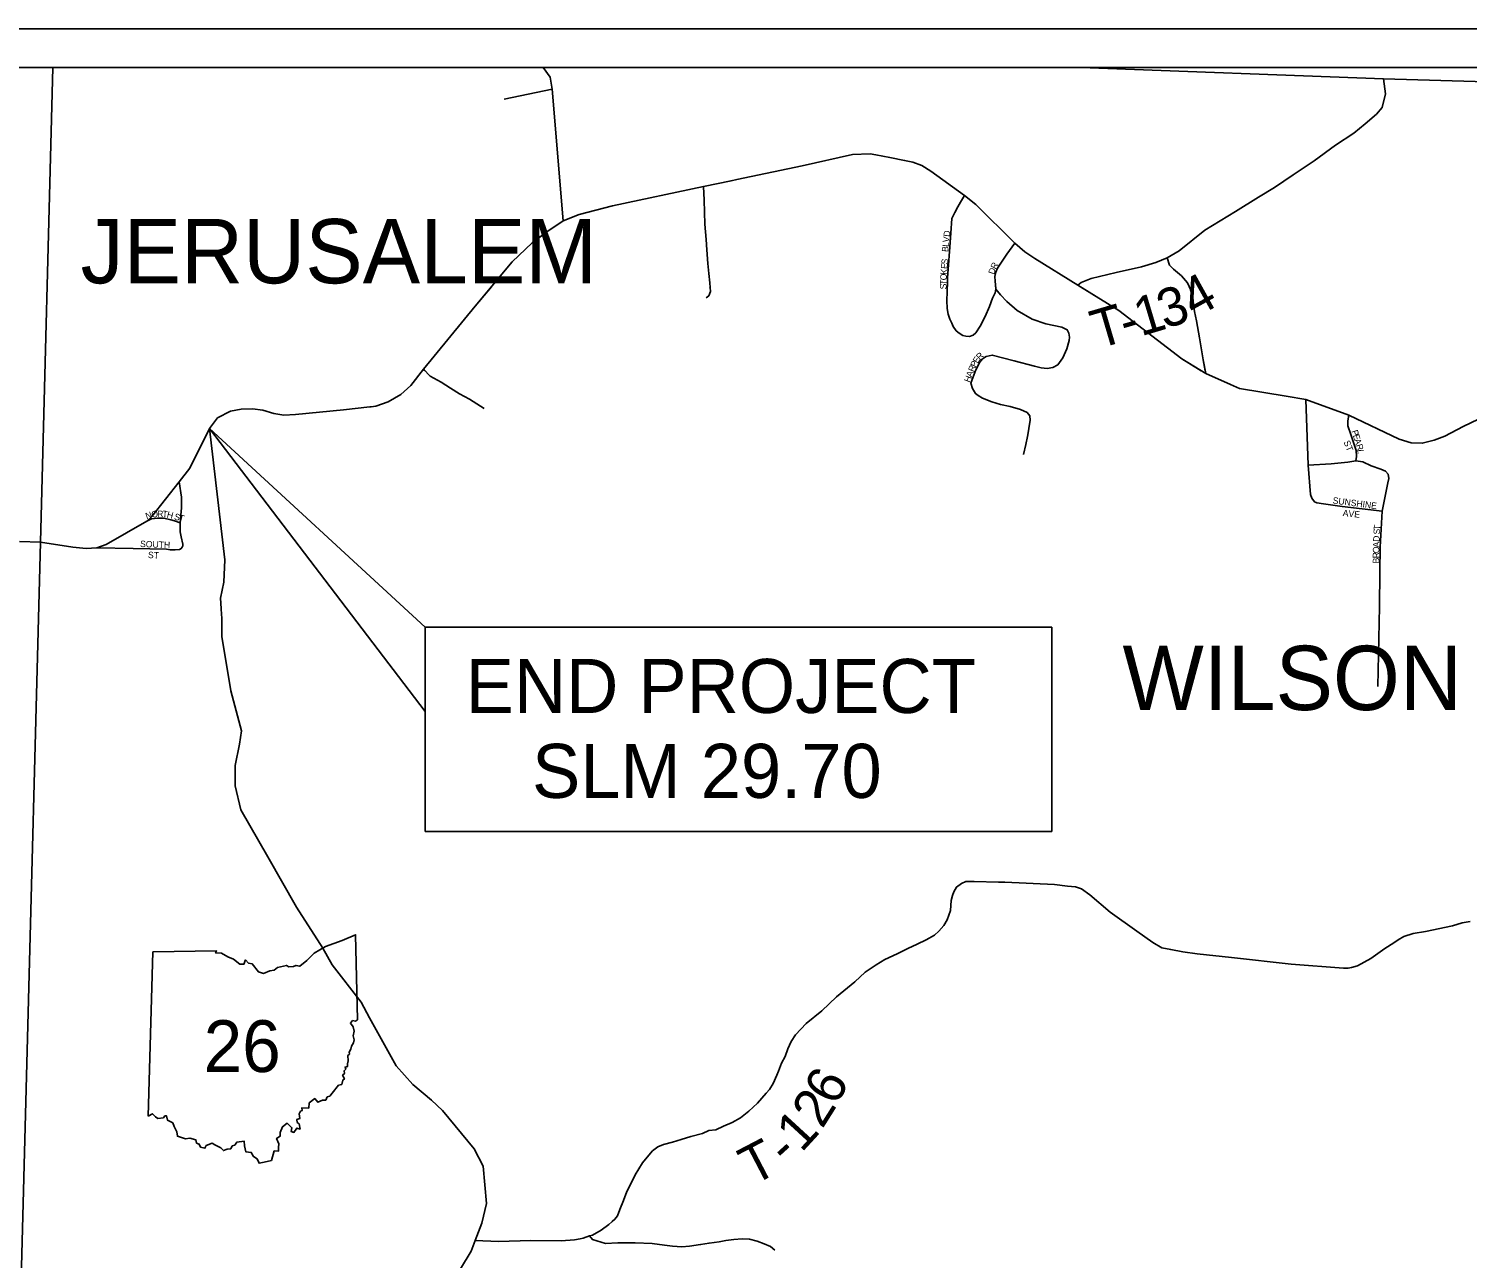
# Model space of a CAD drawing. Extents: x -15 to 405, y -40 to 87.
# Drawn here: x -11.331 to -9.096, y 40.271 to 42.183 of the extents above; entities that cross this region are included whole.
import ezdxf

# ---------------------------------------------------------------- set-up
doc = ezdxf.new("R2010")
doc.units = 0
for name, color, linetype in [('GM_P_State_Location', 7, 'Continuous'), ('GM_X_Airport_Text_Class_2', 7, 'Continuous'), ('GM_X_City_Street_Text', 7, 'Continuous'), ('GM_X_Major_Lake', 7, 'Continuous'), ('GM_X_Major_Lake_Text', 7, 'Continuous'), ('GM_X_Major_River', 7, 'Continuous'), ('GM_X_Minor_River', 7, 'Continuous'), ('GM_X_Rail_Line', 7, 'Continuous'), ('GM_X_State_Location', 7, 'Continuous'), ('GM_X_State_Route', 7, 'Continuous'), ('GM_X_State_Shield', 7, 'Continuous'), ('GM_X_Township_ROW', 7, 'Continuous')]:
    doc.layers.add(name, color=color, linetype=linetype)

msp = doc.modelspace()

# ---------------------------------------------------------------- linework, layer by layer
at = {"layer": 'GM_P_State_Location'}
for points in [[(-9.7009, 41.7839), (-9.6961, 41.7879), (-9.6802, 41.7941), (-9.6414, 41.8038), (-9.6022, 41.8127), (-9.5798, 41.8194), (-9.5624, 41.8265), (-9.5436, 41.8375), (-9.5039, 41.8697), (-9.4561, 41.8984), (-9.4203, 41.9205), (-9.3956, 41.9357), (-9.3666, 41.9553), (-9.334, 41.9774), (-9.3006, 42.0014), (-9.2723, 42.0202), (-9.2545, 42.0349), (-9.237, 42.05), (-9.2283, 42.0601), (-9.223, 42.0814), (-9.226, 42.1046)], [(-10.2826, 41.9373), (-10.2815, 41.9163), (-10.2807, 41.879), (-10.2788, 41.855), (-10.2774, 41.8389), (-10.2759, 41.8177), (-10.2745, 41.8021), (-10.2731, 41.7877), (-10.2726, 41.7805), (-10.2721, 41.7741), (-10.2745, 41.7676), (-10.2784, 41.7644)], [(-9.5032, 41.6509), (-9.5062, 41.6677), (-9.5122, 41.7021), (-9.5169, 41.7285), (-9.5199, 41.7428), (-9.5213, 41.7536), (-9.5218, 41.7609), (-9.5239, 41.7696), (-9.5268, 41.7788), (-9.5309, 41.7876), (-9.5403, 41.7987), (-9.5524, 41.809), (-9.5585, 41.8149), (-9.5624, 41.8265)], [(-10.2727, 41.7814), (-10.2726, 41.7805), (-10.2721, 41.7741), (-10.2745, 41.7676), (-10.2784, 41.7644)], [(-9.5025, 41.6467), (-9.5062, 41.6677), (-9.5122, 41.7021), (-9.5169, 41.7285), (-9.5199, 41.7428), (-9.5213, 41.7536), (-9.5218, 41.7609), (-9.5239, 41.7696), (-9.5268, 41.7788), (-9.528, 41.7814)], [(-10.718, 41.6532), (-10.7072, 41.6424), (-10.6902, 41.6333), (-10.6757, 41.6239), (-10.6619, 41.6153), (-10.6462, 41.607), (-10.6235, 41.5921)], [(-10.718, 41.6532), (-10.7158, 41.6509)], [(-10.4253, 40.3279), (-10.4244, 40.3287), (-10.4204, 40.332), (-10.4165, 40.3373), (-10.4126, 40.3474), (-10.4071, 40.361), (-10.4016, 40.3751), (-10.3958, 40.3872), (-10.3891, 40.4013), (-10.3832, 40.4102), (-10.3777, 40.4199), (-10.3678, 40.4316), (-10.3618, 40.4385), (-10.3539, 40.4446), (-10.3447, 40.4483), (-10.3311, 40.4521), (-10.3175, 40.4558), (-10.3023, 40.4608), (-10.2843, 40.4654), (-10.2743, 40.4699), (-10.2635, 40.4712), (-10.2519, 40.4766), (-10.238, 40.4827), (-10.2252, 40.4897), (-10.2121, 40.5002), (-10.199, 40.5124), (-10.1855, 40.5282), (-10.1804, 40.5339), (-10.1745, 40.5431), (-10.1686, 40.556), (-10.1662, 40.5625), (-10.1616, 40.5749), (-10.1561, 40.585), (-10.1518, 40.5971), (-10.1467, 40.6084), (-10.14, 40.6185), (-10.1233, 40.6363), (-10.0987, 40.6558), (-10.076, 40.6777), (-10.0474, 40.7013), (-10.0315, 40.7159), (-10.0144, 40.7277), (-10.0009, 40.7358), (-9.9817, 40.7445), (-9.9654, 40.7527), (-9.951, 40.7596), (-9.937, 40.7666), (-9.9239, 40.7736), (-9.9171, 40.78), (-9.9092, 40.7889), (-9.9041, 40.7974), (-9.899, 40.8119), (-9.898, 40.8276), (-9.8961, 40.8352), (-9.8937, 40.8408), (-9.8898, 40.8485), (-9.8818, 40.8538), (-9.8754, 40.8571), (-9.8622, 40.8568), (-9.8244, 40.8562)], [(-9.8244, 40.8562), (-9.8169, 40.8561), (-9.8148, 40.856), (-9.7374, 40.8526), (-9.717, 40.8496), (-9.7049, 40.8489), (-9.6957, 40.8458), (-9.6827, 40.8363), (-9.6508, 40.8094), (-9.6096, 40.7798), (-9.5845, 40.762), (-9.5708, 40.7542), (-9.5567, 40.7511), (-9.5378, 40.7477), (-9.5158, 40.7447), (-9.4624, 40.7389), (-9.3696, 40.7287), (-9.2882, 40.7224), (-9.2809, 40.7225), (-9.2757, 40.7233), (-9.2666, 40.7262), (-9.2458, 40.7373), (-9.2243, 40.7528), (-9.2104, 40.7617), (-9.2036, 40.7666), (-9.1945, 40.7715), (-9.1801, 40.7761), (-9.1609, 40.7795), (-9.1192, 40.7884), (-9.104, 40.7926), (-9.0916, 40.7947)], [(-10.6375, 40.2989), (-10.6013, 40.2976), (-10.5512, 40.299), (-10.5039, 40.2987), (-10.483, 40.3001), (-10.4742, 40.3018), (-10.4698, 40.3026), (-10.4599, 40.3064), (-10.4551, 40.3072), (-10.4415, 40.315), (-10.43, 40.3239), (-10.4253, 40.3279)], [(-10.4599, 40.3064), (-10.4554, 40.3008), (-10.4349, 40.2942), (-10.416, 40.2956), (-10.3888, 40.2955), (-10.3627, 40.2942), (-10.3434, 40.2916), (-10.331, 40.2901), (-10.3165, 40.2894), (-10.3045, 40.29), (-10.2873, 40.2926), (-10.2741, 40.2951), (-10.2585, 40.2969), (-10.2481, 40.299), (-10.2357, 40.3007), (-10.2228, 40.3017), (-10.2112, 40.301), (-10.1995, 40.2979), (-10.1883, 40.294), (-10.1786, 40.2897), (-10.1717, 40.2838)]]:
    msp.add_lwpolyline(points, dxfattribs=at)
at = {"layer": 'GM_X_City_Street_Text'}
for points in [[(-9.877, 41.9232), (-9.8833, 41.9131), (-9.8876, 41.9055), (-9.8924, 41.8971), (-9.8968, 41.8878), (-9.8986, 41.8646), (-9.9005, 41.8365), (-9.902, 41.8156), (-9.9035, 41.7952), (-9.9036, 41.7893)], [(-9.8602, 41.6509), (-9.8597, 41.6523), (-9.8534, 41.6644), (-9.8494, 41.6692), (-9.8434, 41.6733), (-9.8342, 41.6753), (-9.8, 41.6663), (-9.7687, 41.6581), (-9.7579, 41.6554), (-9.7487, 41.6546), (-9.7402, 41.6559), (-9.7322, 41.6603), (-9.7243, 41.6708), (-9.7183, 41.6849), (-9.7144, 41.6981), (-9.7142, 41.7031), (-9.7149, 41.7094), (-9.7177, 41.7146), (-9.7262, 41.7185), (-9.7507, 41.724), (-9.7719, 41.7311), (-9.7953, 41.7445), (-9.8114, 41.7585), (-9.8211, 41.7688), (-9.8284, 41.7776), (-9.8292, 41.7844), (-9.8296, 41.7904), (-9.8301, 41.7976), (-9.8285, 41.8041), (-9.8257, 41.8105), (-9.8114, 41.8322), (-9.7991, 41.8495)], [(-9.9036, 41.7893), (-9.9036, 41.7893), (-9.9041, 41.7735), (-9.9045, 41.7603), (-9.904, 41.7475), (-9.9027, 41.7391), (-9.8999, 41.7311), (-9.897, 41.7251), (-9.8946, 41.7199), (-9.8901, 41.7131), (-9.8857, 41.7091), (-9.8797, 41.7059), (-9.8749, 41.7048), (-9.8692, 41.7044), (-9.8636, 41.706), (-9.8597, 41.7101), (-9.8529, 41.7201), (-9.845, 41.7354), (-9.8382, 41.7507), (-9.8335, 41.7635), (-9.8295, 41.772), (-9.8284, 41.7776)], [(-9.9039, 41.7814), (-9.9041, 41.7735), (-9.9045, 41.7603), (-9.904, 41.7475), (-9.9027, 41.7391), (-9.8999, 41.7311), (-9.897, 41.7251), (-9.8946, 41.7199), (-9.8901, 41.7131), (-9.8857, 41.7091), (-9.8797, 41.7059), (-9.8749, 41.7048), (-9.8692, 41.7044), (-9.8636, 41.706), (-9.8597, 41.7101), (-9.8529, 41.7201), (-9.845, 41.7354), (-9.8382, 41.7507), (-9.8335, 41.7635), (-9.8295, 41.772), (-9.8284, 41.7776)], [(-9.7856, 41.5205), (-9.7821, 41.5362), (-9.7793, 41.5486), (-9.7778, 41.5574), (-9.7766, 41.5647), (-9.7758, 41.5703), (-9.7751, 41.5743), (-9.7759, 41.5807), (-9.7799, 41.5863), (-9.79, 41.5906), (-9.8065, 41.5954), (-9.8213, 41.5985), (-9.8346, 41.6028), (-9.849, 41.6083), (-9.8559, 41.6123), (-9.8603, 41.6155), (-9.8648, 41.6231), (-9.8672, 41.6315), (-9.8597, 41.6523), (-9.8534, 41.6644), (-9.8494, 41.6692), (-9.8434, 41.6733), (-9.8342, 41.6753), (-9.8, 41.6663), (-9.7687, 41.6581), (-9.7579, 41.6554), (-9.7487, 41.6546), (-9.7402, 41.6559), (-9.7322, 41.6603), (-9.7243, 41.6708), (-9.7183, 41.6849), (-9.7144, 41.6981), (-9.7142, 41.7031), (-9.7149, 41.7094), (-9.7177, 41.7146), (-9.7262, 41.7185), (-9.7507, 41.724), (-9.7719, 41.7311), (-9.7953, 41.7445), (-9.8114, 41.7585), (-9.8211, 41.7688), (-9.8284, 41.7776), (-9.8288, 41.7814)], [(-11.2251, 41.3759), (-11.1686, 41.3749), (-11.1168, 41.3736), (-11.1112, 41.3728), (-11.1037, 41.3728), (-11.0968, 41.3733), (-11.0941, 41.3746), (-11.0925, 41.3765), (-11.0916, 41.3786), (-11.0916, 41.3814), (-11.0941, 41.393), (-11.0958, 41.4006), (-11.0958, 41.4058), (-11.0956, 41.4146), (-11.094, 41.4379), (-11.0937, 41.4543), (-11.0976, 41.4784)], [(-11.1475, 41.4171), (-11.1404, 41.4208), (-11.1312, 41.4216), (-11.1215, 41.4217), (-11.1147, 41.4205), (-11.1103, 41.4193), (-11.1047, 41.4174), (-11.0956, 41.4146)]]:
    msp.add_lwpolyline(points, dxfattribs=at)
at = {"layer": 'GM_X_Major_Lake_Text'}
msp.add_lwpolyline([(-10.5924, 42.0733), (-10.5178, 42.0887)], dxfattribs=at)
at = {"layer": 'GM_X_Major_River'}
for points in [[(-9.2283, 41.4327), (-9.2902, 41.4399), (-9.3195, 41.4443), (-9.3299, 41.4457), (-9.3332, 41.4473), (-9.3376, 41.4528), (-9.3397, 41.4584), (-9.3431, 41.504), (-9.3471, 41.6061)], [(-9.2691, 41.5111), (-9.268, 41.5175), (-9.2685, 41.5271), (-9.2768, 41.5519), (-9.2818, 41.5654), (-9.2815, 41.5731), (-9.2799, 41.5818)], [(-9.3431, 41.504), (-9.3075, 41.5061), (-9.2819, 41.5089), (-9.2691, 41.5111), (-9.2582, 41.5096), (-9.2453, 41.503), (-9.2304, 41.498), (-9.2231, 41.4949), (-9.2191, 41.4902), (-9.218, 41.4836), (-9.2193, 41.4768), (-9.2283, 41.4327), (-9.2316, 41.3765), (-9.2319, 41.3388)], [(-9.2319, 41.3388), (-9.2319, 41.3379), (-9.2323, 41.2843), (-9.235, 41.1604)]]:
    msp.add_lwpolyline(points, dxfattribs=at)
at = {"layer": 'GM_X_Rail_Line'}
msp.add_lwpolyline([(-5.8735, 37.6193), (-6.746, 37.6435), (-7.1795, 37.6523), (-7.1958, 37.2443), (-7.727, 37.2683), (-7.6952, 37.7971), (-8.9152, 37.8499), (-9.0187, 37.8511), (-9.126, 37.86), (-10.3436, 37.8843), (-11.1424, 37.9093), (-11.1367, 38.1803), (-11.3964, 38.1863), (-11.3573, 39.6853), (-11.313, 41.3844), (-11.2938, 42.1225)], dxfattribs=at)
at = {"layer": 'GM_X_State_Location'}
for p, q in [((-14.8813, 42.1225), (-5.8856, 42.1225)), ((-10.7153, 40.9349), (-10.7153, 41.2523)), ((-10.7153, 41.2523), (-9.7415, 41.2523)), ((-9.7415, 41.2523), (-9.7415, 40.9349)), ((-9.7415, 40.9349), (-10.7153, 40.9349)), ((-11.1455, 40.4922), (-11.1383, 40.7475))]:
    msp.add_line(p, q, dxfattribs=at)
for points in [[(-14.9291, 34.0044), (-14.9414, 42.1825), (-5.8257, 42.1825), (-5.8134, 34.0044)], [(-10.7153, 41.2523), (-11.0504, 41.5612), (-10.7153, 41.1212)]]:
    msp.add_lwpolyline(points, close=True, dxfattribs=at)
for points in [[(-10.5007, 41.884), (-10.5178, 42.0887), (-10.521, 42.1073), (-10.5319, 42.1225)], [(-10.231, 41.9482), (-10.1294, 41.9695), (-10.0511, 41.9873), (-10.0239, 41.9882), (-10.0148, 41.9865), (-9.9933, 41.9823)], [(-9.9933, 41.9823), (-9.9704, 41.9779), (-9.9575, 41.9752), (-9.9436, 41.97), (-9.9297, 41.9614), (-9.877, 41.9232), (-9.8594, 41.9093), (-9.7991, 41.8495), (-9.7837, 41.836), (-9.7678, 41.8256), (-9.7009, 41.7839)], [(-10.5007, 41.884), (-10.476, 41.8936), (-10.4241, 41.9074), (-10.2826, 41.9373), (-10.24, 41.9463), (-10.231, 41.9482)], [(-10.7198, 41.6509), (-10.718, 41.6532), (-10.6377, 41.7511), (-10.58, 41.82), (-10.5487, 41.8496), (-10.5263, 41.867), (-10.5007, 41.884)], [(-10.8009, 41.5948), (-10.7992, 41.5949), (-10.7918, 41.5957), (-10.7724, 41.6025), (-10.7531, 41.6139), (-10.7377, 41.6281), (-10.718, 41.6532), (-10.6377, 41.7511), (-10.6123, 41.7814)], [(-9.7009, 41.7839), (-9.6373, 41.7445), (-9.5394, 41.6697), (-9.5093, 41.6509)], [(-9.6969, 41.7814), (-9.6373, 41.7445), (-9.5394, 41.6697), (-9.5025, 41.6467), (-9.4642, 41.6298)], [(-9.4642, 41.6298), (-9.45, 41.6236), (-9.3776, 41.6116), (-9.3471, 41.6061), (-9.2799, 41.5818), (-9.2017, 41.5446), (-9.1835, 41.539), (-9.166, 41.5383), (-9.1474, 41.5428), (-9.1312, 41.5491), (-9.1026, 41.5644), (-9.0788, 41.5755)], [(-11.0504, 41.5612), (-11.0378, 41.5779), (-11.0178, 41.5881), (-11.0013, 41.5912), (-10.9834, 41.5918), (-10.9672, 41.5897), (-10.9504, 41.5846), (-10.9348, 41.5819), (-10.9166, 41.5828), (-10.8423, 41.5903), (-10.8009, 41.5948)], [(-11.3456, 41.3857), (-11.313, 41.3844), (-11.2628, 41.3768), (-11.2421, 41.3746), (-11.2251, 41.3759), (-11.2109, 41.3807), (-11.1475, 41.4171), (-11.1399, 41.4242), (-11.0976, 41.4784), (-11.0806, 41.4994), (-11.0504, 41.5612)], [(-11.0319, 41.2805), (-11.032, 41.2814), (-11.0331, 41.2977), (-11.0279, 41.3223), (-11.0265, 41.3572), (-11.0504, 41.5612)], [(-10.6602, 40.2548), (-10.6438, 40.2823), (-10.6375, 40.2989), (-10.6273, 40.3259), (-10.6198, 40.3565), (-10.6252, 40.4146), (-10.6393, 40.4416), (-10.6884, 40.5009), (-10.7055, 40.5171), (-10.7344, 40.5414), (-10.7602, 40.5706), (-10.8015, 40.6453), (-10.8147, 40.6695), (-10.8598, 40.7273), (-10.8743, 40.7535), (-10.9151, 40.817), (-10.9597, 40.8952), (-11.0014, 40.9682), (-11.0105, 41.0058), (-11.0106, 41.0371), (-11.0036, 41.0705), (-11.0007, 41.0914), (-11.017, 41.1536), (-11.0313, 41.238), (-11.0309, 41.2661), (-11.0319, 41.2805)], [(-11.1383, 40.7475), (-11.0393, 40.7491), (-11.0408, 40.746), (-11.0315, 40.7454), (-11.0216, 40.7399), (-11.0132, 40.7365), (-11.0029, 40.7284), (-10.9968, 40.7284), (-10.9942, 40.7351), (-10.9895, 40.73), (-10.9839, 40.729), (-10.9742, 40.7168), (-10.9663, 40.7142), (-10.9567, 40.7184), (-10.9496, 40.7191), (-10.9444, 40.7232), (-10.9308, 40.7267), (-10.927, 40.7246), (-10.9198, 40.7251), (-10.9161, 40.7266), (-10.9099, 40.7252), (-10.8989, 40.7345), (-10.8875, 40.7455), (-10.87, 40.7558), (-10.8439, 40.7655), (-10.8232, 40.7743), (-10.8202, 40.6418)], [(-10.8202, 40.6418), (-10.8233, 40.64), (-10.828, 40.6408), (-10.8312, 40.6371), (-10.8272, 40.6309), (-10.8254, 40.6244), (-10.827, 40.6172), (-10.8254, 40.6112), (-10.8265, 40.6062), (-10.8295, 40.6013), (-10.8305, 40.5966), (-10.8331, 40.5916), (-10.8329, 40.5888), (-10.8352, 40.5866), (-10.8348, 40.5783), (-10.836, 40.5737), (-10.8356, 40.5697), (-10.8396, 40.5687), (-10.8386, 40.5654), (-10.8411, 40.5629), (-10.8406, 40.5586), (-10.8435, 40.5558), (-10.8407, 40.5502), (-10.8429, 40.5485), (-10.8447, 40.5417), (-10.8498, 40.5403), (-10.8598, 40.528), (-10.8634, 40.5233), (-10.8674, 40.5221), (-10.8696, 40.5173), (-10.8745, 40.5173), (-10.882, 40.514), (-10.8868, 40.5197), (-10.8952, 40.5128), (-10.8961, 40.5048), (-10.9068, 40.5051), (-10.9064, 40.5011), (-10.9088, 40.4999), (-10.9109, 40.4959), (-10.9097, 40.4887), (-10.9147, 40.4869), (-10.9141, 40.4827), (-10.9108, 40.4802), (-10.9094, 40.4722), (-10.9147, 40.4738), (-10.9191, 40.4671), (-10.9236, 40.4687), (-10.9221, 40.4744), (-10.9296, 40.4812), (-10.9368, 40.4758), (-10.9405, 40.467), (-10.9405, 40.4611), (-10.9459, 40.4576), (-10.9424, 40.4493), (-10.9431, 40.4436), (-10.943, 40.4381), (-10.9496, 40.4384), (-10.9537, 40.4236)], [(-10.9537, 40.4236), (-10.9652, 40.4208), (-10.9732, 40.4192), (-10.9761, 40.4258), (-10.9818, 40.4294), (-10.9855, 40.436), (-10.9938, 40.437), (-10.9957, 40.4462), (-10.9966, 40.4536), (-11.0079, 40.4518), (-11.011, 40.4472), (-11.015, 40.446), (-11.0173, 40.4414), (-11.0228, 40.441), (-11.0286, 40.4388), (-11.0324, 40.4433), (-11.042, 40.4479), (-11.0463, 40.4502), (-11.0553, 40.4466), (-11.0573, 40.4423), (-11.0644, 40.4442), (-11.0661, 40.449), (-11.0704, 40.4505), (-11.0714, 40.4555), (-11.0806, 40.4583), (-11.0877, 40.4572), (-11.1002, 40.4612), (-11.101, 40.4679), (-11.1052, 40.4761), (-11.1074, 40.4817), (-11.1153, 40.486), (-11.117, 40.4928), (-11.1195, 40.4926), (-11.1218, 40.4899), (-11.1306, 40.4886), (-11.1341, 40.4913), (-11.139, 40.4961), (-11.1455, 40.4922)]]:
    msp.add_lwpolyline(points, dxfattribs=at)
at = {"layer": 'GM_X_State_Route'}
msp.add_lwpolyline([(-5.8852, 41.8593), (-6.0144, 41.8658), (-7.0055, 41.8974), (-6.9927, 42.0179), (-7.1063, 42.0243), (-7.8445, 42.0517), (-8.0815, 42.0605), (-8.6025, 42.0864), (-9.226, 42.1046), (-9.6959, 42.1225)], dxfattribs=at)

# ---------------------------------------------------------------- texts
at = {"layer": 'GM_X_Airport_Text_Class_2'}
for s, rotation, p in [('V', 83.8457, (-9.9011, 41.8501)), ('D', 83.8239, (-9.9001, 41.8588)), ('B', 84.6495, (-9.9026, 41.8352)), ('L', 83.868, (-9.9018, 41.8431)), ('E', 84.8006, (-9.904, 41.8088)), ('S', 84.7734, (-9.9033, 41.8158)), ('R', 62.6204, (-9.8285, 41.8078)), ('O', 87.3111, (-9.9051, 41.7913)), ('K', 85.1637, (-9.9047, 41.8)), ('D', 71.0535, (-9.8312, 41.7998)), ('S', 89.5902, (-9.9052, 41.7774)), ('T', 89.5628, (-9.9052, 41.7844)), ('R', 67.4231, (-9.8628, 41.6483)), ('P', 63.6427, (-9.8598, 41.6554)), ('P', 63.6427, (-9.8598, 41.6554)), ('E', 57.2648, (-9.8568, 41.6615)), ('E', 57.2648, (-9.8568, 41.6615)), ('R', 43.6949, (-9.8534, 41.6669)), ('R', 43.6949, (-9.8534, 41.6669)), ('H', 69.1241, (-9.869, 41.6319)), ('A', 69.1037, (-9.8659, 41.6401)), ('N', 18.5041, (-11.1478, 41.4199)), ('O', 6.3957, (-11.14, 41.4226)), ('R', 0.4129, (-11.1315, 41.4235)), ('T', 355.5426, (-11.1238, 41.4236)), ('H', 345.0573, (-11.1173, 41.4231)), ('S', 344.2841, (-11.1059, 41.4199)), ('T', 346.2869, (-11.0988, 41.4179)), ('SOUTH', 357.5069, (-11.1583, 41.377)), ('ST', 356.4118, (-11.1461, 41.3599))]:
    msp.add_text(s, height=0.01, rotation=rotation, dxfattribs=at).set_placement(p)
at = {"layer": 'GM_X_Major_Lake'}
for s, rotation, p in [('P', 287.5969, (-9.2761, 41.5571)), ('E', 287.5708, (-9.274, 41.5504)), ('ST', 291.7989, (-9.2885, 41.5403)), ('A', 287.5796, (-9.2719, 41.5437)), ('R', 287.5816, (-9.2692, 41.5353)), ('L', 273.9649, (-9.2669, 41.5284)), ('SUNSHINE', 352.5664, (-9.3057, 41.4447)), ('AVE', 354.0969, (-9.2899, 41.4251)), ('D', 87.1354, (-9.2325, 41.3848)), ('S', 87.0872, (-9.2319, 41.3962)), ('T', 87.0475, (-9.2315, 41.4032)), ('O', 89.8251, (-9.2328, 41.3673)), ('R', 89.8279, (-9.2329, 41.3594)), ('A', 87.8142, (-9.2328, 41.376)), ('B', 89.83, (-9.2329, 41.3515))]:
    msp.add_text(s, height=0.01, rotation=rotation, dxfattribs=at).set_placement(p)
at = {"layer": 'GM_X_Minor_River'}
for s, rotation, p in [('4', 29.0753, (-9.5197, 41.7319)), ('3', 18.3212, (-9.566, 41.7154)), ('T', 16.4193, (-9.6701, 41.6845)), ('T', 16.4193, (-9.6701, 41.6845)), ('1', 16.6626, (-9.6032, 41.7042)), ('1', 16.6626, (-9.6032, 41.7042)), ('-', 16.4543, (-9.6271, 41.6972)), ('-', 16.4543, (-9.6271, 41.6972)), ('6', 62.0862, (-10.0763, 40.5068)), ('2', 57.8561, (-10.0983, 40.4713)), ('1', 47.403, (-10.1306, 40.4346)), ('T', 27.5234, (-10.2065, 40.3836)), ('-', 42.2775, (-10.153, 40.4139))]:
    msp.add_text(s, height=0.06, rotation=rotation, dxfattribs=at).set_placement(p)
at = {"layer": 'GM_X_State_Location'}
for s, p in [('END PROJECT', (-10.6522, 41.119)), ('SLM 29.70', (-10.5491, 40.987))]:
    msp.add_text(s, height=0.084, dxfattribs=at).set_placement(p)
at = {"layer": 'GM_X_State_Shield'}
msp.add_text('26', height=0.08048, dxfattribs=at).set_placement((-11.0593, 40.5609))
at = {"layer": 'GM_X_Township_ROW'}
for s, p in [('JERUSALEM', (-11.2506, 41.7868)), ('WILSON', (-9.6317, 41.1235))]:
    msp.add_text(s, height=0.1, rotation=0, dxfattribs=at).set_placement(p)

doc.saveas('drawing.dxf')
